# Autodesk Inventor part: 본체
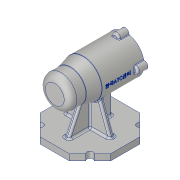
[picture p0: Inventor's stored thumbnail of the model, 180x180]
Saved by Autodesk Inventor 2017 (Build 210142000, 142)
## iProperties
Created: 2019-12
Part Number: 본체
Material: 알루미늄 6061
Document SubType Name: Modeling
Designer: 5-06-le-1
Density: 2.7 g/cm^3
Appearance: 알루미늄 - 평지
Mass: 725.805 g
Surface Area: 714.68 cm^2
Volume: 268.817 cm^3
Author: 5-06-le-1
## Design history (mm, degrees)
sketch "스케치2"
  geometry: L1 (0, 56)-(0, -56); L2 (0, 56)-(25, 56); L3 (25, 56)-(25, 31); L4 (30, 11)-(30, -56); L5 (30, -56)-(21, -56); L6 (0, 50)-(10.5, 50); L7 (10.5, 50)-(10.5, 47); L8 (10.5, 47)-(16, 47); L9 (16, 47)-(16, 43); L10 (16, 43)-(17.5, 43); L11 (17.5, 43)-(17.5, 25); L12 (17.5, 25)-(21, 25); L13 (21, 25)-(21, 13); L14 (21, 13)-(24, 13); L15 (24, 13)-(24, -41); L16 (24, -41)-(21, -41); L17 (21, -41)-(21, -56); L18 (30, 11)-(25, 31); L19 (0, 56)-(0, 50); 1 further point
  constraints: 39 end point, 7 perpendicular, 5 horizontal, 3 vertical, 1 parallel
  dimensions: "d0" = 50 diameter of L3 L1; "d1" = 60 diameter of L4 L1; "d3" = 21 diameter of L7 L1; "d4" = 32 diameter of L9 L1; "d5" = 35 diameter of L11 L1; "d6" = 42 diameter of L13 L1; "d7" = 48 diameter of L15 L1; "d8" = 42 diameter of L17 L1; "d9" = 3 distance of L6.end L7.end; "d10" = 4 distance of L8.end L9.end; "d11" = 18 distance of L10.end L11.end; "d12" = 12 distance of L12.end L13.end; "d13" = 54 distance of L14.end L15.end; "d14" = 15 distance of L5.end L16.end; "d15" = 25 distance of L2.end L3.end; "d16" = 45 vertical distance of L4.start L2.end; "d17" = 112 distance between parallel lines of L5 L2; "d31" = 112 distance of L1.start L1.end; "d32" = 56 vertical distance of L5.end point (0, 0)
revolve "회전1" sketch "스케치2" stored, may be unused: angle "d18" = 90 deg
fillet "모깎기1" dims "d19" = 10
fillet "모깎기2" dims "d20" = 3
fillet "모깎기3" dims "d21" = 0.3
fillet "모깎기4" dims "d22" = 3
chamfer "모따기1" distance "d24" = 1; stored, may be unused: second distance "d25" = 2, angle "d26" = 45 deg
node "작업 평면1"
sketch "스케치3"
  geometry: L1 (56, -23.196)-(23.196, -56); L2 (23.196, -56)-(-23.196, -56); L3 (-23.196, -56)-(-56, -23.196); L4 (-56, -23.196)-(-56, 23.196); L5 (-56, 23.196)-(-23.196, 56); L6 (-23.196, 56)-(23.196, 56); L7 (23.196, 56)-(56, 23.196); L8 (56, 23.196)-(56, -23.196); L9 (-30, -56)-(30, -56) reference; 3 further points
  constraints: 16 end point, 1 collinear, 1 midpoint, 17 other
extrude "돌출1" join sketch "스케치3" distance "d29" = 10; taper "d30" = 0 deg
sketch "스케치5"
  geometry: L1 (18.549, -22.052)-(36, -70); L2 (23.196, -70)-(56, -70) reference; L3 (-18.303, -21.377)-(-36, -70); L4 (-56, -70)-(-23.196, -70) reference; L5 (56, -80)-(56, -70) reference; L6 (-56, -80)-(-56, -70) reference; L7 (18.549, -22.052)-(0, -27.139); L8 (0, -27.139)-(-18.303, -21.377); L9 (36, -70)-(-36, -70); 1 further point
  constraints: 10 end point, 2 point on line
  dimensions: "d37" = 20 distance from line of L5 L1.end; "d38" = 20 distance from line of L6 L3.end; "d39" = 110 deg angle of L2 L1; "d40" = 110 deg angle of L4 L3
extrude "돌출2" join sketch "스케치5" stored distance "d41" = 8; taper "d42" = 0 deg
fillet "모깎기5" dims "d43" = 3
sketch "스케치6"
  geometry: L1 (-23.39, 16.265)-(-70, 38); L2 (-70, 23.196)-(-70, 56) reference; L3 (-80, 56)-(-70, 56) reference; 1 further point
  constraints: 2 end point, 1 point on line
  dimensions: "d44" = 18 distance from line of L1.end L3; "d45" = 115 deg angle of L2 L1
feature "리브1" sketch "스케치6" dims "d46" = 1, "d47" = 8, "d48" = 0, "d49" = 0, "d50" = 1, "d51" = 1
fillet "모깎기6" dims "d52" = 3
sketch "스케치7"
  geometry: L1 (-25.271, -31)-(-70, -31); L2 (-70, 23.196)-(-70, -23.196) reference; L3 (-80, -56)-(-70, -56) reference; 1 further point
  constraints: 2 end point, 1 horizontal, 1 point on line
  dimensions: "d53" = 25 distance between parallel lines of L3 L1
feature "리브2" sketch "스케치7" dims "d54" = 1, "d55" = 8, "d56" = 0, "d57" = 0, "d58" = 1, "d59" = 1
fillet "모깎기7" dims "d60" = 3
fillet "모깎기8" dims "d61" = 3
fillet "모깎기9" dims "d62" = 3
sketch "스케치8"
  geometry: L1 (23.196, -56)-(56, -23.196) reference; L2 (56, 23.196)-(23.196, 56) reference; L3 (-23.196, 56)-(-56, 23.196) reference; L4 (-56, -23.196)-(-23.196, -56) reference; C1 r 5 at (39.598, -39.598); C2 r 5 at (-39.598, -39.598); C3 r 5 at (39.598, 39.598); C4 r 5 at (-39.598, 39.598); 1 further point
  constraints: 4 centre point, 4 midpoint, 3 equal radius
  dimensions: "d63" = 10 diameter of C1
extrude "돌출3" cut sketch "스케치8" distance "d64" = 23; taper "d65" = 0 deg
fillet "모깎기10" dims "d66" = 3
sketch "스케치9"
  geometry: C1 r 6 at (0, 30); 4 further points
  constraints: 1 centre point, 1 vertical alignment, 3 other
  dimensions: "d67" = 12 diameter of C1
extrude "돌출4" join sketch "스케치9" distance "d68" = 16; taper "d69" = 0 deg
sketch "스케치10"
  geometry: A1 r 6 centre (0, 0) between (5.97, -0.6) and (-5.97, -0.6) reference; 1 further point
  constraints: 1 coincident
hole "구멍1" sketch "스케치10" at (0, 0) diameter "d70" = 3.242; stored, may be unused: countersink angle "d74" = 90 deg, drill point angle "d76" = 118 deg; dims "d71" = 8, "d72" = 4, "d73" = 2, "d75" = 11
fillet "모깎기11" dims "d80" = 3
fillet "모깎기12" dims "d81" = 1
node "작업 평면2"
sketch "스케치11"
  geometry: L1 (8.916, 30.867)-(8.916, -15.067); L2 (8.916, -15.067)-(-8.916, -15.067); L3 (-8.916, -15.067)-(-8.916, 30.867); L4 (-8.916, 30.867)-(8.916, 30.867); L5 (8.916, -15.067)-(8.916, 30.867); L6 (-8.916, 7.9)-(8.916, 7.9); L7 (0, 30.867)-(0, -15.067); L8 (6.771, -33.5)-(29.226, -33.5) reference; L9 (5.998, -33.5)-(-5.998, -33.5) reference; L10 (0, -33.5)-(0, 79.188); 1 further point
  constraints: 8 end point, 5 midpoint, 2 coincident, 1 collinear, 1 perpendicular, 2 other
  dimensions: "d82" = 41.4 distance between parallel lines of L8 L6
feature "엠보싱1" sketch "스케치11" dims "d0" = 50, "d1" = 60, "d3" = 21, "d4" = 32, "d5" = 35, "d6" = 42, "d7" = 48, "d8" = 42, "d9" = 3, "d10" = 4, "d11" = 18, "d12" = 12, "d13" = 54, "d14" = 15, "d15" = 25, "d16" = 45, "d17" = 112, "d31" = 112, "d32" = 56, "d83" = 0.5, "d84" = 0
node "솔리드1"
pattern_circular "원형 패턴1" dims angle "d78" = 360 deg
